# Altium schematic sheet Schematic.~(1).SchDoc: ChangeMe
size 431 x 279 mm; Date: Not shown in title block; ApprovedBy: Not shown in title block; CheckedBy: Not shown in title block; Author: Not shown in title block; CompanyName: Not shown in title block; DrawnBy: Enter Full Name; Engineer: Not shown in title block; Organization: Not shown in title block; Address1: Not shown in title block; Address2: Not shown in title block; Address3: Not shown in title block; Address4: Not shown in title block; DocumentNumber: 2; Revision: Use project parameter SCH_Rev; SheetNumber: 2; SheetTotal: 3; PageSetup: Record=PageOptions|CenterHorizontal=True|CenterVertical=True|PrintScale=1.00|XCorrection=1.00|YCorrection=1.00|PrintKind=0|BorderSize=5000000|LeftOffset=0|BottomOffset=0|Orientation=2|PaperLength=1000|PaperWidth=1000|Scale=100|PaperSource=15|PrintQuality=600|MediaType=1|DitherType=10|PaperKind=Letter|PrintScaleMode=1
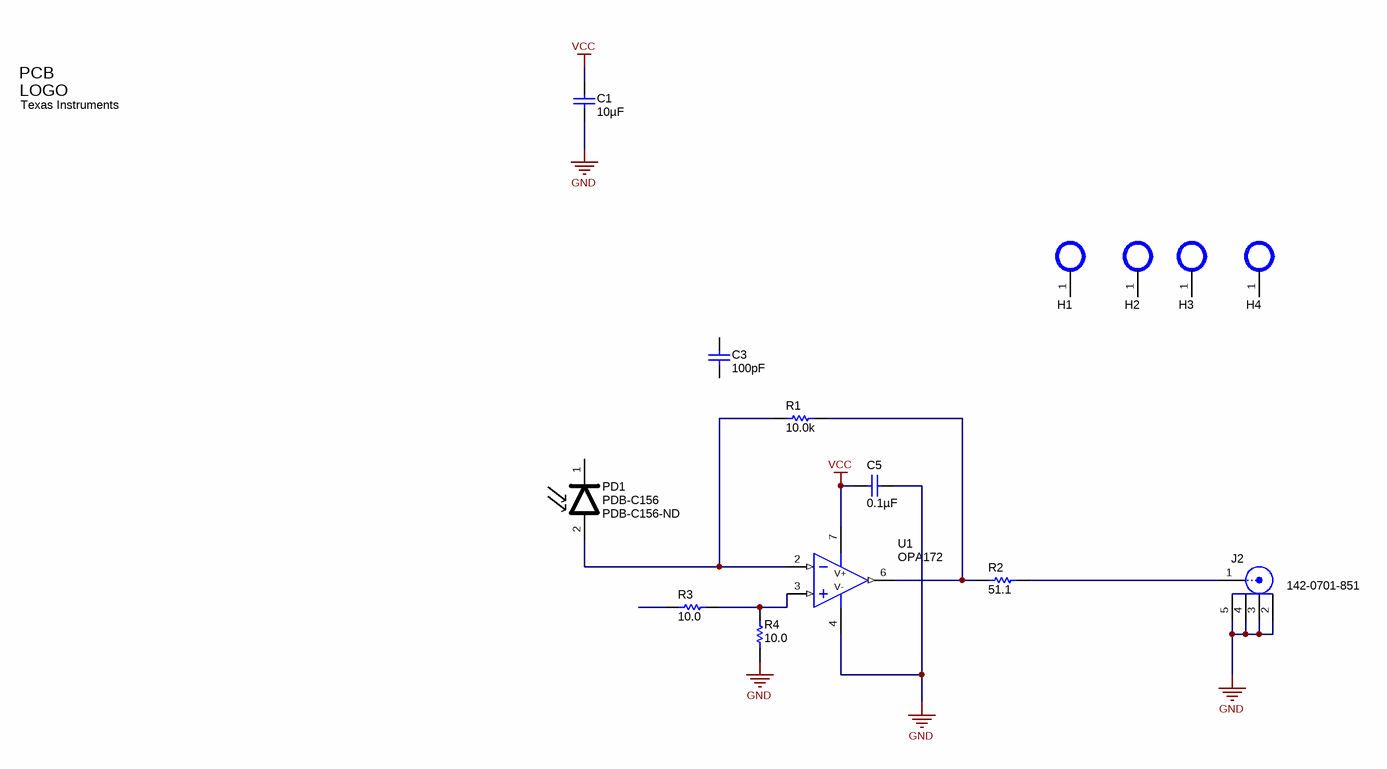
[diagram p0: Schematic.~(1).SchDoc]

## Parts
C1  ValueDisplayed: 10µF  [1210]  (hidden comment: C1210C106K8PACTU)
C3  ValueDisplayed: 100pF  [0603]  (hidden comment: 06033C101KAT2A)
C5  ValueDisplayed: 0.1µF  [0603]  (hidden comment: 0603YC104JAT2A)
H1  NA  [Mounting Hole]  (value not drawn)  (no BOM)
H2  NA  [Mounting Hole]  (value not drawn)  (no BOM)
H3  NA  [Mounting Hole]  (value not drawn)  (no BOM)
H4  NA  [Mounting Hole]  (value not drawn)  (no BOM)
J2  142-0701-851  [Emerson_142-0701-851]
Logo1  Texas Instruments  [TI_Stacked_Overlay_Small]  (no BOM)
PD1  PDB-C156  Supplier Part Number 1: PDB-C156-ND  [PDB-C156]
R1  value 10.0k  [0603]  (hidden comment: CRCW060310K0FKEA)
R2  value 51.1  [0603]  (hidden comment: CRCW060351R1FKEA)
R3  value 10.0  [0603]  (hidden comment: CRCW060310R0FKEA)
R4  value 10.0  [0603]  (hidden comment: CRCW060310R0FKEA)
U1  OPA172  [M08A_M]

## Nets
GND: C1.2 C5.1 J2.2 J2.3 J2.4 J2.5 R4.1 U1.4(V-)
VCC: C1.1 C5.2 U1.7(V+)
NetJ2_1: J2.1 R2.2
NetPD1_2: PD1.2(A) R1.1 U1.2(IN-)
NetR1_2: R1.2 R2.1 U1.6(OUT)
NetR3_2: R3.2 R4.2 U1.3(IN+)

Not connected (* = marked no-connect by the designer): C3 1 2; H1 1; H2 1; H3 1; H4 1; PD1 1(C); R3 1

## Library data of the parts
C1 = C1210C106K8PACTU: CAP, CERM, 10uF, 10V, +/-10%, X5R, 1210; Manufacturer: Kemet; Polarized: N; CompType: Capacitor; U/M: EA; Cap_F: 0.00001; Tolerance_%: 10; ESR_Ohm: 0.008; Value1: 0.008 ohm; IRMS_A: 6.9; TaMin_C: -55; TaMax_C: 85
C3 = 06033C101KAT2A: CAP, CERM, 100pF, 25V, +/-10%, X7R, 0603; Manufacturer: AVX; Polarized: N; CompType: Capacitor; U/M: EA; Cap_F: 0.0000000001; Tolerance_%: 10; VDC_V: 25; TaMin_C: -55; TaMax_C: 125
C5 = 0603YC104JAT2A: CAP, CERM, 0.1uF, 16V, +/-5%, X7R, 0603; Manufacturer: AVX; Polarized: N; CompType: Capacitor; U/M: EA; Cap_F: 0.0000001; Tolerance_%: 5; ESR_Ohm: 0.039; Value1: 0.039 ohm; VDC_V: 16; TaMin_C: -55; TaMax_C: 125
H1-H4 = Mounting Hole: Manufacturer: Used in BOM report; SymbolVersion: use current date i.e. 2008-05-20; SymbolCreator: Use LDAP id; CompType: Used in some BOM reports.  Useful for finding later.; U/M: EA, IN, or GM
J2 = 142-0701-851: Connector, SMT, End launch SMA 50 ohm; Manufacturer: Emerson Network Power; Alternate Manufacturer: Any; Alternate PartNumber: Equivalent; U/M: EA
Logo1 = TI_Logo: Texas Instrument Corporate Signature; SymbolCreator: codlsc
PD1 = PDB-C156: Photodiode; Manufacturer: Used in BOM report; SymbolVersion: use current date i.e. 2008-05-20; SymbolCreator: Use LDAP id; CompType: Used in some BOM reports.  Useful for finding later.; U/M: EA, IN, or GM
R1 = CRCW060310K0FKEA: RES, 10.0k ohm, 1%, 0.1W, 0603; Manufacturer: Vishay-Dale; Alternate Manufacturer: Any; Alternate PartNumber: Equivalent; CompType: Resistor; Res_ohm: 10000; Value_Code: 10k0; Tolerance_%: 1; Power_W: 0.1; VDC_V: 75; TempCo: 100 ppm/C; EIA_Code: E96; U/M: EA
R2 = CRCW060351R1FKEA: RES, 51.1 ohm, 1%, 0.1W, 0603; Manufacturer: Vishay-Dale; Alternate Manufacturer: Any; Alternate PartNumber: Equivalent; CompType: Resistor; Value_Code: 51R1; Tolerance_%: 1; Power_W: 0.1; VDC_V: 75; TempCo: 100 ppm/C; EIA_Code: E96; U/M: EA
R3 R4 = CRCW060310R0FKEA: RES, 10.0 ohm, 1%, 0.1W, 0603; Manufacturer: Vishay-Dale; Alternate Manufacturer: Any; Alternate PartNumber: Equivalent; CompType: Resistor; Res_ohm: 10; Value_Code: 10R0; Tolerance_%: 1; Power_W: 0.1; VDC_V: 75; TempCo: 100 ppm/C; EIA_Code: E96; U/M: EA
U1 = OPA172: Manufacturer: Used in BOM report; SymbolVersion: use current date i.e. 2008-05-20; SymbolCreator: Use LDAP id; CompType: Used in some BOM reports.  Useful for finding later.; U/M: EA, IN, or GM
